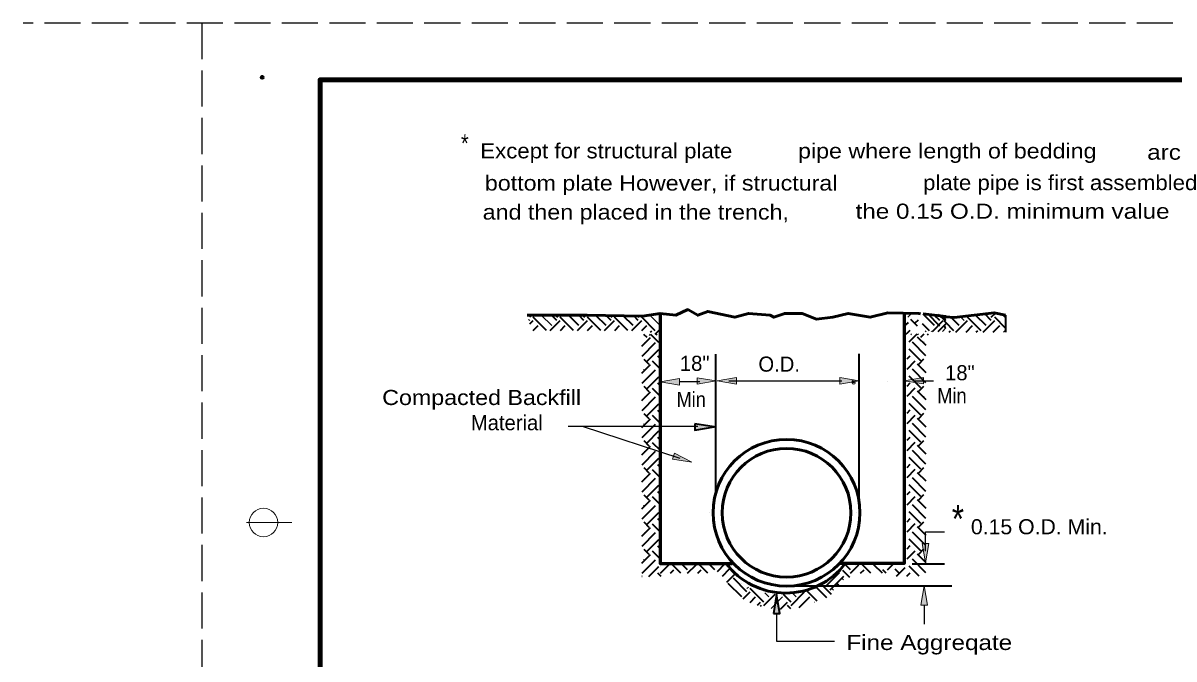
# Model space of a CAD drawing. Extents: x 36.1 to 71.5, y 0.2 to 22.2.
# Drawn here: x 36.14 to 46.27, y 16.61 to 22.21 of the extents above; entities that cross this region are included whole.
import ezdxf

# ---------------------------------------------------------------- set-up
doc = ezdxf.new("R2010")
doc.units = 0
doc.header["$LTSCALE"] = 0.053
doc.header["$PDMODE"] = 32
doc.header["$PDSIZE"] = 0.0265
doc.linetypes.add('LONG_DASHED', pattern=[7.5, 6, -1.5])
for name, color, linetype, lineweight in [('1', 7, 'Continuous', 35), ('3', 7, 'Continuous', 25), ('6', 7, 'Continuous', 13)]:
    doc.layers.add(name, color=color, linetype=linetype, lineweight=lineweight)

msp = doc.modelspace()

# ---------------------------------------------------------------- hatches: boundary and pattern name
at = {"layer": '1'}
for points in [[(41.91525, 19.02433), (41.91525, 19.08067), (41.74625, 19.0525), (41.74625, 19.0525)], [(42.0695, 19.03225), (42.0695, 19.08858), (42.2385, 19.06042), (42.2385, 19.06042)], [(42.41542, 19.03275), (42.41542, 19.08917), (42.24642, 19.061), (42.24642, 19.061)], [(43.32683, 19.03275), (43.32683, 19.08917), (43.49583, 19.061), (43.49583, 19.061)], [(44.10842, 17.62808), (44.05208, 17.62808), (44.08025, 17.45908), (44.08025, 17.45908)], [(44.09642, 17.08583), (44.04008, 17.08583), (44.06825, 17.25483), (44.06825, 17.25483)]]:
    msp.add_hatch(color=256, dxfattribs=at).paths.add_polyline_path(points)
at = {"layer": '3'}
for points in [[(44.061, 19.03408), (44.061, 19.09042), (43.892, 19.06217), (43.892, 19.06217)], [(42.04992, 18.68283), (42.04992, 18.6265), (42.21892, 18.65467), (42.21892, 18.65467)], [(41.85392, 18.37058), (41.87125, 18.424), (42.02325, 18.34458), (42.02325, 18.34458)], [(42.74142, 17.01075), (42.7975, 17.01075), (42.7695, 17.17975), (42.7695, 17.17975)]]:
    msp.add_hatch(color=256, dxfattribs=at).paths.add_polyline_path(points)

# ---------------------------------------------------------------- linework, layer by layer
at = {"layer": '1', "linetype": 'LONG_DASHED', "lineweight": 25}
for p, q in [((71.33717, 22.21317), (36.13717, 22.21317)), ((37.71217, 22.21317), (37.71217, 0.21317))]:
    msp.add_line(p, q, dxfattribs=at)
at = {"layer": '1', "lineweight": 158}
for p, q in [((38.75383, 21.71317), (38.75383, 0.71317)), ((71.25383, 21.71317), (38.75383, 21.71317))]:
    msp.add_line(p, q, dxfattribs=at)
at = {"layer": '1', "lineweight": 53}
for p, q in [((43.74983, 19.66033), (44.02058, 19.65317)), ((44.02058, 19.65317), (44.03558, 19.65142)), ((44.05992, 19.65142), (44.2605, 19.62858)), ((44.25083, 19.62858), (44.25933, 19.62758))]:
    msp.add_line(p, q, dxfattribs=at)
at = {"layer": '1', "lineweight": 13}
for p, q in [((43.78958, 19.65525), (43.78558, 19.65925)), ((43.88492, 19.64967), (43.87767, 19.65692)), ((44.03542, 19.6485), (44.03217, 19.65175)), ((40.59625, 19.59217), (40.58642, 19.60208)), ((40.59625, 19.62208), (40.61317, 19.639)), ((40.7905, 19.54742), (40.69883, 19.639)), ((41.74625, 19.54767), (41.6535, 19.64042)), ((41.74625, 19.63725), (41.73233, 19.65133)), ((43.92483, 19.62183), (43.94858, 19.64567)), ((44.20567, 19.62208), (44.217, 19.63342)), ((44.25217, 19.61842), (44.2605, 19.62683)), ((44.42025, 19.59217), (44.38808, 19.62442)), ((44.42025, 19.62208), (44.42742, 19.62917)), ((44.78533, 19.6155), (44.75583, 19.64508)), ((43.95017, 19.46783), (43.95733, 19.47508)), ((44.00992, 19.46783), (44.01717, 19.47508)), ((44.13067, 19.49708), (44.13258, 19.499)), ((44.22892, 19.49708), (44.25933, 19.5275)), ((44.76608, 19.48983), (44.77883, 19.50267)), ((44.06517, 19.40225), (44.06625, 19.40342)), ((44.06517, 18.92425), (44.06625, 18.92542)), ((38.50383, 17.81317), (38.10383, 17.81317)), ((41.79133, 17.44117), (41.78083, 17.45175)), ((42.03025, 17.44117), (42.01992, 17.45175)), ((42.26925, 17.44117), (42.25883, 17.45175)), ((43.46433, 17.44117), (43.45392, 17.45175)), ((42.4635, 17.27683), (42.46358, 17.27708)), ((42.50833, 17.23208), (42.52133, 17.24517)), ((43.27017, 17.21708), (43.25517, 17.23208)), ((43.358, 17.30858), (43.34475, 17.32175)), ((42.7025, 17.15742), (42.66533, 17.1945)), ((42.72083, 17.05625), (42.822, 17.15742)), ((42.94158, 17.15742), (42.91217, 17.18675)), ((42.98625, 17.20217), (42.98567, 17.20275)), ((43.10383, 17.11067), (43.10583, 17.11258))]:
    msp.add_line(p, q, dxfattribs=at)
at = {"layer": '1'}
for p, q in [((44.65942, 19.62208), (44.69508, 19.65783)), ((40.59783, 19.56392), (40.62608, 19.59217)), ((40.74433, 19.504), (40.62608, 19.62208)), ((40.777, 19.504), (40.86517, 19.59217)), ((40.83542, 19.59217), (40.78858, 19.639)), ((40.83542, 19.62208), (40.85217, 19.639)), ((40.98325, 19.504), (40.86517, 19.62208)), ((41.0295, 19.54742), (40.938, 19.639)), ((41.01592, 19.504), (41.10417, 19.59217)), ((41.07433, 19.59217), (41.0275, 19.639)), ((41.07433, 19.62208), (41.09117, 19.639)), ((41.22225, 19.504), (41.10417, 19.62208)), ((41.2685, 19.54742), (41.17808, 19.63783)), ((41.25492, 19.504), (41.34317, 19.59217)), ((41.31325, 19.59217), (41.269, 19.63642)), ((41.31325, 19.62208), (41.32683, 19.63575)), ((41.46133, 19.504), (41.34317, 19.62208)), ((41.5075, 19.54742), (41.42058, 19.63442)), ((41.494, 19.504), (41.58217, 19.59217)), ((41.55242, 19.59217), (41.51158, 19.633)), ((41.55242, 19.62208), (41.5625, 19.63225)), ((41.70158, 19.50267), (41.58217, 19.62208)), ((43.90758, 19.55342), (43.929, 19.57483)), ((44.00883, 19.54225), (43.9505, 19.6005)), ((43.99042, 19.57167), (44.01858, 19.59992)), ((44.11492, 19.50267), (44.05367, 19.56383)), ((44.15967, 19.54742), (44.05858, 19.6485)), ((44.20725, 19.54375), (44.09933, 19.65158)), ((44.14042, 19.49708), (44.2355, 19.59217)), ((44.20567, 19.59217), (44.15767, 19.64025)), ((44.1905, 19.49708), (44.2605, 19.56708)), ((44.25217, 19.5885), (44.19467, 19.646)), ((44.25933, 19.59708), (44.23433, 19.62208)), ((44.25933, 19.57392), (44.24467, 19.58858)), ((44.25933, 19.58858), (44.25083, 19.59708)), ((44.33075, 19.50267), (44.25933, 19.57392)), ((44.3755, 19.54742), (44.30183, 19.62108)), ((44.34775, 19.48983), (44.45025, 19.59217)), ((44.56967, 19.50267), (44.45025, 19.62208)), ((44.6145, 19.54742), (44.52133, 19.6405)), ((44.58683, 19.48983), (44.68917, 19.59217)), ((44.65942, 19.59217), (44.60133, 19.65025)), ((44.78533, 19.526), (44.68917, 19.62208)), ((44.78533, 19.526), (44.68917, 19.62208)), ((44.78533, 19.639), (44.78533, 19.48983)), ((40.62758, 19.504), (40.671, 19.54742)), ((40.86658, 19.504), (40.90992, 19.54742)), ((41.1055, 19.504), (41.14908, 19.54742)), ((41.34467, 19.504), (41.388, 19.54742)), ((41.58358, 19.504), (41.62692, 19.54742)), ((41.62975, 19.44258), (41.60167, 19.47067)), ((41.659, 19.46342), (41.65175, 19.47067)), ((41.65825, 19.48908), (41.67183, 19.50267)), ((41.73258, 19.39942), (41.6615, 19.47067)), ((41.70158, 19.47267), (41.74625, 19.51733)), ((41.71875, 19.46342), (41.71158, 19.47067)), ((43.886, 19.45092), (43.94375, 19.5085)), ((43.93633, 19.40383), (44.00742, 19.47508)), ((44.03917, 19.447), (44.06725, 19.47508)), ((44.08058, 19.49708), (44.08617, 19.50267)), ((44.09842, 19.46783), (44.10567, 19.47508)), ((44.24467, 19.536), (44.25608, 19.54742)), ((44.25083, 19.5275), (44.25933, 19.536)), ((44.288, 19.48983), (44.30083, 19.50267)), ((44.4375, 19.48983), (44.495, 19.54742)), ((44.52692, 19.48983), (44.53983, 19.50267)), ((44.67642, 19.48983), (44.73408, 19.54742)), ((41.58383, 19.36675), (41.65958, 19.44258)), ((41.58383, 19.36675), (41.65958, 19.44258)), ((41.58492, 19.27833), (41.70442, 19.39783)), ((41.60375, 19.39783), (41.60267, 19.399)), ((44.084, 19.28275), (43.9645, 19.40225)), ((44.08508, 19.37117), (44.00933, 19.447)), ((44.08508, 19.37117), (44.00933, 19.447)), ((41.64858, 19.20367), (41.60267, 19.24958)), ((41.62975, 19.23342), (41.73258, 19.33642)), ((41.75142, 19.25), (41.72325, 19.27833)), ((42.23458, 18.07767), (42.23458, 19.29658)), ((43.49692, 17.97983), (43.49692, 19.2985)), ((43.9175, 19.25442), (43.94567, 19.28275)), ((44.03917, 19.23783), (43.93633, 19.34083)), ((44.02033, 19.20808), (44.06625, 19.254)), ((41.58383, 19.12783), (41.65958, 19.20367)), ((41.58492, 19.03933), (41.70442, 19.15875)), ((41.60375, 19.15875), (41.60267, 19.16)), ((41.75142, 19.1605), (41.67842, 19.23342)), ((43.9175, 19.16492), (43.9905, 19.23783)), ((44.084, 19.04375), (43.9645, 19.16317)), ((44.08508, 19.13225), (44.00933, 19.20808)), ((44.06517, 19.16317), (44.06625, 19.16442)), ((41.62975, 18.9945), (41.73258, 19.0975)), ((44.03917, 18.99892), (43.93633, 19.10192)), ((41.58383, 18.88892), (41.65958, 18.96467)), ((41.64858, 18.96467), (41.60267, 19.01067)), ((41.75142, 18.92158), (41.67842, 18.9945)), ((41.75142, 19.01108), (41.72325, 19.03933)), ((43.9175, 19.0155), (43.94567, 19.04375)), ((43.9175, 18.926), (43.9905, 18.99892)), ((44.08508, 18.89333), (44.00933, 18.96908)), ((44.02033, 18.96908), (44.06625, 19.01508)), ((41.58492, 18.80033), (41.70442, 18.91983)), ((41.60375, 18.91983), (41.60267, 18.921)), ((41.62975, 18.75558), (41.73258, 18.85842)), ((44.03917, 18.76), (43.93633, 18.86283)), ((44.084, 18.80475), (43.9645, 18.92425)), ((41.64858, 18.72567), (41.60267, 18.77167)), ((41.75142, 18.68242), (41.67842, 18.75558)), ((41.75142, 18.77208), (41.72325, 18.80033)), ((43.9175, 18.7765), (43.94567, 18.80475)), ((43.9175, 18.68683), (43.9905, 18.76)), ((44.02033, 18.73008), (44.06625, 18.77608)), ((41.58383, 18.64975), (41.65958, 18.72567)), ((41.58492, 18.56133), (41.70442, 18.68092)), ((41.60375, 18.68092), (41.60267, 18.682)), ((44.084, 18.56575), (43.9645, 18.68533)), ((44.08508, 18.65417), (44.00933, 18.73008)), ((41.62975, 18.51642), (41.73258, 18.61942)), ((41.75142, 18.533), (41.72325, 18.56133)), ((43.9175, 18.53742), (43.94567, 18.56575)), ((44.03917, 18.52083), (43.93633, 18.62383)), ((41.58383, 18.41083), (41.65958, 18.48667)), ((41.58492, 18.32233), (41.70442, 18.44175)), ((41.64858, 18.48667), (41.60267, 18.53258)), ((41.60375, 18.44175), (41.60267, 18.443)), ((41.75142, 18.4435), (41.67842, 18.51642)), ((43.9175, 18.44792), (43.9905, 18.52083)), ((44.084, 18.32675), (43.9645, 18.44617)), ((44.08508, 18.41525), (44.00933, 18.49108)), ((44.02033, 18.49108), (44.06625, 18.537)), ((41.62975, 18.2775), (41.73258, 18.3805)), ((44.03917, 18.28192), (43.93633, 18.38492)), ((41.58383, 18.17175), (41.65958, 18.24767)), ((41.64858, 18.24767), (41.60267, 18.29367)), ((41.75142, 18.20442), (41.67842, 18.2775)), ((41.75142, 18.29408), (41.72325, 18.32233)), ((43.9175, 18.2985), (43.94567, 18.32675)), ((43.9175, 18.20883), (43.9905, 18.28192)), ((44.08508, 18.17617), (44.00933, 18.25208)), ((44.02033, 18.25208), (44.06625, 18.29808)), ((41.58492, 18.08333), (41.70442, 18.20283)), ((41.60375, 18.20283), (41.60267, 18.204)), ((41.62975, 18.0385), (41.73258, 18.14133)), ((44.03917, 18.04292), (43.93633, 18.14575)), ((44.084, 18.08775), (43.9645, 18.20725)), ((41.64858, 18.00867), (41.60267, 18.05467)), ((41.75142, 17.96542), (41.67842, 18.0385)), ((41.75142, 18.05517), (41.72325, 18.08333)), ((43.9175, 18.05958), (43.94567, 18.08775)), ((43.9175, 17.96983), (43.9905, 18.04292)), ((44.02033, 18.01308), (44.06625, 18.05908)), ((41.58383, 17.93275), (41.65958, 18.00867)), ((41.58492, 17.84433), (41.70442, 17.96392)), ((41.60375, 17.96392), (41.60267, 17.965)), ((44.084, 17.84875), (43.9645, 17.96833)), ((44.08508, 17.93717), (44.00933, 18.01308)), ((41.62975, 17.7995), (41.73258, 17.90242)), ((41.75142, 17.81608), (41.72325, 17.84433)), ((43.9175, 17.8205), (43.94567, 17.84875)), ((44.03917, 17.80392), (43.93633, 17.90683)), ((41.58383, 17.69375), (41.65958, 17.76958)), ((41.64858, 17.76958), (41.60267, 17.81558)), ((41.75142, 17.72642), (41.67842, 17.7995)), ((43.9175, 17.73083), (43.9905, 17.80392)), ((44.084, 17.60975), (43.9645, 17.72917)), ((44.08508, 17.69817), (44.00933, 17.774)), ((44.02033, 17.774), (44.06625, 17.82)), ((41.58492, 17.60533), (41.70442, 17.72475)), ((41.60375, 17.72475), (41.60267, 17.726)), ((41.62975, 17.5605), (41.73258, 17.6635)), ((44.03917, 17.56492), (43.93633, 17.66792)), ((41.58383, 17.45475), (41.65958, 17.53067)), ((41.64858, 17.53067), (41.60267, 17.57658)), ((41.75142, 17.4875), (41.67842, 17.5605)), ((41.75142, 17.57708), (41.72325, 17.60533)), ((43.9175, 17.5815), (43.94567, 17.60975)), ((43.9175, 17.49192), (43.9905, 17.56492)), ((44.08508, 17.45917), (44.00933, 17.53508)), ((44.02033, 17.53508), (44.06625, 17.581)), ((41.58492, 17.36633), (41.70442, 17.48583)), ((41.60375, 17.48583), (41.60267, 17.487)), ((41.6445, 17.33633), (41.73258, 17.42433)), ((41.74633, 17.36642), (41.82117, 17.44117)), ((41.92583, 17.36642), (41.84067, 17.45175)), ((41.9855, 17.39642), (41.93025, 17.45175)), ((41.98542, 17.36642), (42.06017, 17.44117)), ((42.16483, 17.36642), (42.07967, 17.45175)), ((42.22458, 17.39642), (42.16917, 17.45175)), ((42.24808, 17.38225), (42.3145, 17.44858)), ((43.4195, 17.39642), (43.36425, 17.45175)), ((43.41933, 17.36642), (43.49417, 17.44117)), ((43.59883, 17.36642), (43.51367, 17.45175)), ((43.70075, 17.36642), (43.626, 17.44117)), ((43.74533, 17.39642), (43.80058, 17.45175)), ((44.02442, 17.34075), (43.93633, 17.42875)), ((43.96183, 17.44833), (44.24725, 17.44833)), ((44.084, 17.37075), (43.9645, 17.49025)), ((41.585, 17.33633), (41.58383, 17.33767)), ((41.75325, 17.33633), (41.72325, 17.36633)), ((41.75325, 17.33633), (41.72325, 17.36633)), ((41.83608, 17.36642), (41.86608, 17.39642)), ((42.075, 17.36642), (42.105, 17.39642)), ((42.2935, 17.34192), (42.35575, 17.40417)), ((42.33042, 17.28908), (42.39758, 17.35625)), ((43.20417, 17.25308), (43.32367, 17.37267)), ((43.24108, 17.22017), (43.3605, 17.33967)), ((43.41425, 17.32792), (43.35183, 17.39025)), ((43.50908, 17.36642), (43.53908, 17.39642)), ((43.73375, 17.36642), (43.70375, 17.39642)), ((43.845, 17.37075), (43.813, 17.40283)), ((43.82617, 17.34075), (43.90092, 17.4155)), ((43.91567, 17.34075), (43.94567, 17.37075)), ((43.91567, 17.34075), (43.94567, 17.37075)), ((42.4635, 17.15742), (42.344, 17.27683)), ((42.50833, 17.20217), (42.38883, 17.32175)), ((42.65775, 17.11258), (42.53817, 17.23208)), ((42.91017, 17.25483), (44.31158, 17.25483)), ((43.21208, 17.1495), (43.12575, 17.23583)), ((43.253, 17.17842), (43.17975, 17.25167)), ((43.31617, 17.26075), (43.3, 17.27683)), ((42.47642, 17.14042), (42.53817, 17.20217)), ((42.53575, 17.11008), (42.583, 17.15742)), ((42.65775, 17.08267), (42.75575, 17.18075)), ((42.89667, 17.11258), (42.83042, 17.17883)), ((42.89667, 17.08267), (43.01625, 17.20217)), ((42.96933, 17.06567), (43.061, 17.15742)), ((43.12683, 17.12158), (43.031, 17.21733)), ((42.60017, 17.08492), (42.62775, 17.11258)), ((42.63675, 17.07375), (42.62775, 17.08267)), ((42.8035, 17.04933), (42.86683, 17.11258)), ((42.89617, 17.05342), (42.86683, 17.08267))]:
    msp.add_line(p, q, dxfattribs=at)
at = {"layer": '1', "lineweight": 25}
for p, q in [((42.09442, 19.0525), (41.91525, 19.0525)), ((42.34825, 19.061), (43.34267, 19.061)), ((44.08033, 17.56142), (44.08033, 17.73042)), ((44.08033, 17.73042), (44.24825, 17.73042)), ((44.06825, 17.08583), (44.06825, 16.91683))]:
    msp.add_line(p, q, dxfattribs=at)
at = {"layer": '1', "lineweight": 53}
for points in [[(40.57533, 19.639), (41.10325, 19.639), (41.5905, 19.63183), (41.74625, 19.65317)], [(41.74625, 19.65317), (41.88408, 19.63867), (41.98783, 19.68892), (42.07558, 19.63867), (42.16342, 19.67217), (42.40275, 19.622), (42.5225, 19.65542), (42.714, 19.63867), (42.74592, 19.622), (42.84175, 19.65542), (42.99317, 19.65542), (43.12108, 19.60517), (43.26467, 19.622), (43.40025, 19.65542), (43.59183, 19.622), (43.74983, 19.66033)], [(44.33183, 19.61767), (44.68383, 19.66033), (44.78533, 19.639)], [(44.24467, 19.62758), (44.25933, 19.62592), (44.33183, 19.61767)]]:
    msp.add_lwpolyline(points, dxfattribs=at)
at = {"layer": '1', "lineweight": 60}
for points in [[(41.74625, 19.65317), (41.74625, 17.45175), (42.37883, 17.45175)], [(43.89275, 19.653), (43.89275, 17.45158), (43.31892, 17.45158)]]:
    msp.add_lwpolyline(points, dxfattribs=at)
at = {"layer": '1', "lineweight": 13}
for points in [[(41.91525, 19.02433), (41.91525, 19.08067), (41.74625, 19.0525), (41.74625, 19.0525)], [(42.0695, 19.03225), (42.0695, 19.08858), (42.2385, 19.06042), (42.2385, 19.06042)], [(42.41542, 19.03275), (42.41542, 19.08917), (42.24642, 19.061), (42.24642, 19.061)], [(43.32683, 19.03275), (43.32683, 19.08917), (43.49583, 19.061), (43.49583, 19.061)], [(44.10842, 17.62808), (44.05208, 17.62808), (44.08025, 17.45908), (44.08025, 17.45908)], [(44.09642, 17.08583), (44.04008, 17.08583), (44.06825, 17.25483), (44.06825, 17.25483)]]:
    msp.add_lwpolyline(points, close=True, dxfattribs=at)
at = {"layer": '1', "lineweight": 53}
for radius in [0.64645, 0.56664]:
    msp.add_circle((42.85697, 17.89913), radius, dxfattribs=at)
at = {"layer": '1', "lineweight": 13}
msp.add_circle((38.25383, 17.81317), 0.125, dxfattribs=at)
at = {"layer": '1', "lineweight": 53}
msp.add_arc((42.85016, 17.84726), 0.65572, 216.61725, 323.07876, dxfattribs=at)
at = {"layer": '1'}
for p in [(38.24183, 21.73317), (38.75383, 21.71317)]:
    msp.add_point(p, dxfattribs=at)
at = {"layer": '3', "lineweight": 13}
msp.add_line((43.74983, 19.0525), (43.74992, 19.0525), dxfattribs=at)
at = {"layer": '3'}
for p, q in [((43.98208, 19.06217), (44.15108, 19.06217)), ((42.07542, 18.65808), (40.93617, 18.65808)), ((41.922, 18.37758), (41.06117, 18.65992))]:
    msp.add_line(p, q, dxfattribs=at)
at = {"layer": '3', "lineweight": 13}
for points in [[(44.061, 19.03408), (44.061, 19.09042), (43.892, 19.06217), (43.892, 19.06217)], [(41.85392, 18.37058), (41.87125, 18.424), (42.02325, 18.34458), (42.02325, 18.34458)]]:
    msp.add_lwpolyline(points, close=True, dxfattribs=at)
at = {"layer": '3', "lineweight": 35}
for points in [[(42.04992, 18.68283), (42.04992, 18.6265), (42.21892, 18.65467), (42.21892, 18.65467)], [(42.74142, 17.01075), (42.7975, 17.01075), (42.7695, 17.17975), (42.7695, 17.17975)]]:
    msp.add_lwpolyline(points, close=True, dxfattribs=at)
at = {"layer": '3'}
msp.add_lwpolyline([(42.7695, 17.01075), (42.7695, 16.76675), (43.2805, 16.76675)], dxfattribs=at)
at = {"layer": '6'}
for p, q in [((42.17925, 19.0525), (42.17933, 19.0525)), ((43.47217, 19.061), (43.47233, 19.061)), ((42.17925, 17.90133), (42.17933, 17.90133)), ((43.47217, 17.90133), (43.47233, 17.90133)), ((42.82567, 17.25483), (42.82583, 17.25483))]:
    msp.add_line(p, q, dxfattribs=at)
at = {"layer": '6', "lineweight": 35}
for p, q in [((41.71842, 17.428), (41.71833, 17.428)), ((41.75142, 17.42433), (41.75133, 17.42433))]:
    msp.add_line(p, q, dxfattribs=at)
at = {"layer": '6'}
for p in [(43.4475, 19.05683), (43.4475, 19.04417)]:
    msp.add_point(p, dxfattribs=at)

# ---------------------------------------------------------------- texts
at = {"layer": '1'}
msp.add_text('O.D.', height=0.133, dxfattribs=at).set_placement((42.60942, 19.14208))
at = {"layer": '3'}
for s, height, width, p in [('*', 0.1536, 0.85, (39.99167, 21.0775)), ('Except for structural plate', 0.133, 1.1, (40.16158, 21.02083)), ('pipe where length of bedding', 0.133, 1.15, (42.95817, 21.02008)), ('arc need not exceed width of', 0.133, 1.2, (46.03142, 21.00892)), ('bottom plate However, if structural', 0.133, 1.15, (40.20192, 20.73708)), ('plate pipe is first assembled', 0.133, 1.1, (44.05875, 20.74075)), ('and then placed in the trench,', 0.133, 1.15, (40.18292, 20.48125)), ('the 0.15 O.D. minimum value', 0.133, 1.2, (43.46433, 20.489)), ('Compacted Backfill', 0.133, 1.15, (39.29825, 18.84808)), ('Min', 0.133, 0.9, (41.88883, 18.83108)), ('Min', 0.133, 0.9, (44.18408, 18.86417)), ('*', 0.2434, 0.85, (44.31142, 17.72375)), ('0.15 O.D. Min.', 0.133, 1.05, (44.47967, 17.70958)), ('Fine Aggreqate', 0.133, 1.2, (43.38358, 16.69008))]:
    msp.add_text(s, height=height, dxfattribs=dict(at, width=width)).set_placement(p)
for s, p in [('18"', (41.91825, 19.14908)), ('18"', (44.25233, 19.06608)), ('Material', (40.07883, 18.62608))]:
    msp.add_text(s, height=0.133, dxfattribs=at).set_placement(p)

doc.saveas('drawing.dxf')
